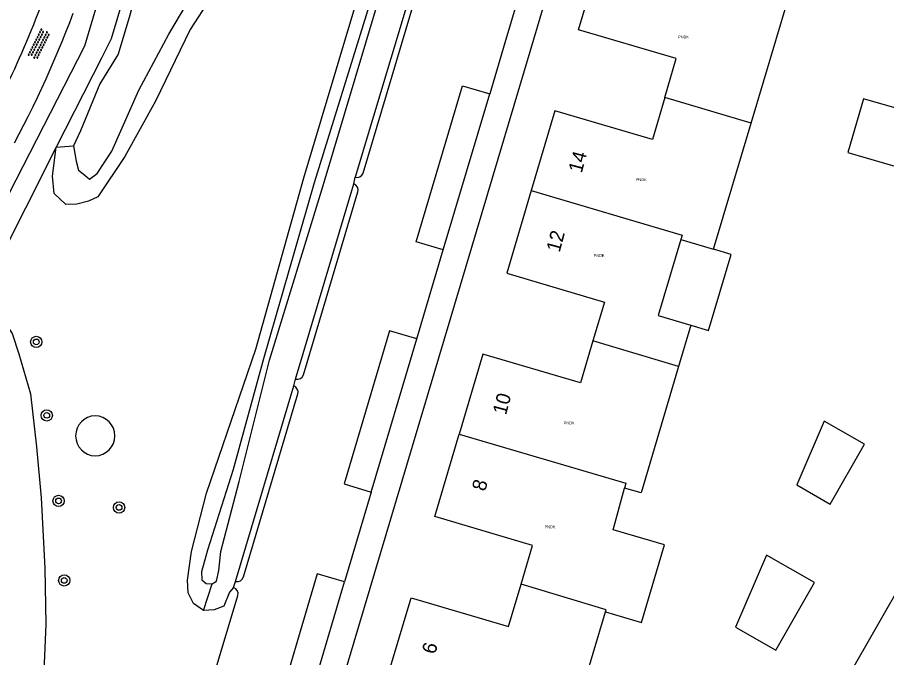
# Model space of a CAD drawing. Extents: x 131000 to 133013, y 393000 to 396501.
# Drawn here: x 131784.2 to 131845.9, y 393529.3 to 393574.7 of the extents above; entities that cross this region are included whole.
import ezdxf

# ---------------------------------------------------------------- set-up
doc = ezdxf.new("R2010")
doc.units = 0
for name, color, linetype in [('gg-anno-huisnummerreeks BGT', 7, 'Continuous'), ('gg-bbg-luifel en loopbrug', 7, 'Continuous'), ('gg-knt-onverhard', 7, 'Continuous'), ('gg-kwrk-kunstwerk niveau 01', 7, 'Continuous'), ('gt-symb-boom', 7, 'Continuous'), ('gt-symb-overige verharding', 7, 'Continuous'), ('gx-grn-maaiveld', 7, 'Continuous'), ('kenmerkpunt-x pandkandidaat', 7, 'Continuous')]:
    doc.layers.add(name, color=color, linetype=linetype)

# ---------------------------------------------------------------- blocks, each defined once
blk = doc.blocks.new('gt0-BOOM')
at = {"layer": 'gt-symb-boom'}
for radius in [0.4, 0.2]:
    blk.add_circle((0, 0), radius, dxfattribs=at)
blk = doc.blocks.new('gt0-OVH')
at = {"layer": 'gt-symb-overige verharding'}
for points in [[(-0.972, 0.298), (-0.967, 0.308), (-0.965, 0.319), (-0.966, 0.33), (-0.971, 0.34), (-0.978, 0.348), (-0.988, 0.353), (-0.999, 0.355), (-1.01, 0.354), (-1.02, 0.349), (-1.028, 0.342), (-1.033, 0.332), (-1.035, 0.321), (-1.034, 0.31), (-1.029, 0.3), (-1.022, 0.292), (-1.012, 0.287), (-1.001, 0.285), (-0.99, 0.286), (-0.98, 0.291)], [(-0.872, 0.106), (-0.867, 0.116), (-0.865, 0.126), (-0.866, 0.137), (-0.871, 0.147), (-0.878, 0.156), (-0.888, 0.161), (-0.899, 0.163), (-0.91, 0.162), (-0.92, 0.157), (-0.928, 0.15), (-0.933, 0.14), (-0.935, 0.129), (-0.934, 0.118), (-0.929, 0.108), (-0.922, 0.1), (-0.912, 0.095), (-0.901, 0.092), (-0.89, 0.094), (-0.88, 0.098)], [(-0.772, 0.298), (-0.767, 0.308), (-0.765, 0.319), (-0.766, 0.33), (-0.771, 0.34), (-0.778, 0.348), (-0.788, 0.353), (-0.799, 0.355), (-0.81, 0.354), (-0.82, 0.349), (-0.828, 0.342), (-0.833, 0.332), (-0.835, 0.321), (-0.834, 0.31), (-0.829, 0.3), (-0.822, 0.292), (-0.812, 0.287), (-0.801, 0.285), (-0.79, 0.286), (-0.78, 0.291)], [(-0.672, 0.106), (-0.667, 0.116), (-0.665, 0.126), (-0.666, 0.137), (-0.671, 0.147), (-0.678, 0.156), (-0.688, 0.161), (-0.699, 0.163), (-0.71, 0.162), (-0.72, 0.157), (-0.728, 0.15), (-0.733, 0.14), (-0.735, 0.129), (-0.734, 0.118), (-0.729, 0.108), (-0.722, 0.1), (-0.712, 0.095), (-0.701, 0.092), (-0.69, 0.094), (-0.68, 0.098)], [(-0.572, 0.298), (-0.567, 0.308), (-0.565, 0.319), (-0.566, 0.33), (-0.571, 0.34), (-0.578, 0.348), (-0.588, 0.353), (-0.599, 0.355), (-0.61, 0.354), (-0.62, 0.349), (-0.628, 0.342), (-0.633, 0.332), (-0.635, 0.321), (-0.634, 0.31), (-0.629, 0.3), (-0.622, 0.292), (-0.612, 0.287), (-0.601, 0.285), (-0.59, 0.286), (-0.58, 0.291)], [(-0.472, 0.106), (-0.467, 0.116), (-0.465, 0.126), (-0.466, 0.137), (-0.471, 0.147), (-0.478, 0.156), (-0.488, 0.161), (-0.499, 0.163), (-0.51, 0.162), (-0.52, 0.157), (-0.528, 0.15), (-0.533, 0.14), (-0.535, 0.129), (-0.534, 0.118), (-0.529, 0.108), (-0.522, 0.1), (-0.512, 0.095), (-0.501, 0.092), (-0.49, 0.094), (-0.48, 0.098)], [(-0.372, 0.298), (-0.367, 0.308), (-0.365, 0.319), (-0.366, 0.33), (-0.371, 0.34), (-0.378, 0.348), (-0.388, 0.353), (-0.399, 0.355), (-0.41, 0.354), (-0.42, 0.349), (-0.428, 0.342), (-0.433, 0.332), (-0.435, 0.321), (-0.434, 0.31), (-0.429, 0.3), (-0.422, 0.292), (-0.412, 0.287), (-0.401, 0.285), (-0.39, 0.286), (-0.38, 0.291)], [(-0.272, 0.106), (-0.267, 0.116), (-0.265, 0.126), (-0.266, 0.137), (-0.271, 0.147), (-0.278, 0.156), (-0.288, 0.161), (-0.299, 0.163), (-0.31, 0.162), (-0.32, 0.157), (-0.328, 0.15), (-0.333, 0.14), (-0.335, 0.129), (-0.334, 0.118), (-0.329, 0.108), (-0.322, 0.1), (-0.312, 0.095), (-0.301, 0.092), (-0.29, 0.094), (-0.28, 0.098)], [(-0.172, 0.298), (-0.167, 0.308), (-0.165, 0.319), (-0.166, 0.33), (-0.171, 0.34), (-0.178, 0.348), (-0.188, 0.353), (-0.199, 0.355), (-0.21, 0.354), (-0.22, 0.349), (-0.228, 0.342), (-0.233, 0.332), (-0.235, 0.321), (-0.234, 0.31), (-0.229, 0.3), (-0.222, 0.292), (-0.212, 0.287), (-0.201, 0.285), (-0.19, 0.286), (-0.18, 0.291)], [(-0.072, 0.106), (-0.067, 0.116), (-0.065, 0.126), (-0.066, 0.137), (-0.071, 0.147), (-0.078, 0.156), (-0.088, 0.161), (-0.099, 0.163), (-0.11, 0.162), (-0.12, 0.157), (-0.128, 0.15), (-0.133, 0.14), (-0.135, 0.129), (-0.134, 0.118), (-0.129, 0.108), (-0.122, 0.1), (-0.112, 0.095), (-0.101, 0.092), (-0.09, 0.094), (-0.08, 0.098)], [(0.028, 0.298), (0.033, 0.308), (0.035, 0.319), (0.034, 0.33), (0.029, 0.34), (0.022, 0.348), (0.012, 0.353), (0.001, 0.355), (-0.01, 0.354), (-0.02, 0.349), (-0.028, 0.342), (-0.033, 0.332), (-0.035, 0.321), (-0.034, 0.31), (-0.029, 0.3), (-0.022, 0.292), (-0.012, 0.287), (-0.001, 0.285), (0.01, 0.286), (0.02, 0.291)], [(0.128, 0.106), (0.133, 0.116), (0.135, 0.126), (0.134, 0.137), (0.129, 0.147), (0.122, 0.156), (0.112, 0.161), (0.101, 0.163), (0.09, 0.162), (0.08, 0.157), (0.072, 0.15), (0.067, 0.14), (0.065, 0.129), (0.066, 0.118), (0.071, 0.108), (0.078, 0.1), (0.088, 0.095), (0.099, 0.092), (0.11, 0.094), (0.12, 0.098)], [(0.228, 0.298), (0.233, 0.308), (0.235, 0.319), (0.234, 0.33), (0.229, 0.34), (0.222, 0.348), (0.212, 0.353), (0.201, 0.355), (0.19, 0.354), (0.18, 0.349), (0.172, 0.342), (0.167, 0.332), (0.165, 0.321), (0.166, 0.31), (0.171, 0.3), (0.178, 0.292), (0.188, 0.287), (0.199, 0.285), (0.21, 0.286), (0.22, 0.291)], [(0.328, 0.106), (0.333, 0.116), (0.335, 0.126), (0.334, 0.137), (0.329, 0.147), (0.322, 0.156), (0.312, 0.161), (0.301, 0.163), (0.29, 0.162), (0.28, 0.157), (0.272, 0.15), (0.267, 0.14), (0.265, 0.129), (0.266, 0.118), (0.271, 0.108), (0.278, 0.1), (0.288, 0.095), (0.299, 0.092), (0.31, 0.094), (0.32, 0.098)], [(0.428, 0.298), (0.433, 0.308), (0.435, 0.319), (0.434, 0.33), (0.429, 0.34), (0.422, 0.348), (0.412, 0.353), (0.401, 0.355), (0.39, 0.354), (0.38, 0.349), (0.372, 0.342), (0.367, 0.332), (0.365, 0.321), (0.366, 0.31), (0.371, 0.3), (0.378, 0.292), (0.388, 0.287), (0.399, 0.285), (0.41, 0.286), (0.42, 0.291)], [(0.528, 0.106), (0.533, 0.116), (0.535, 0.126), (0.534, 0.137), (0.529, 0.147), (0.522, 0.156), (0.512, 0.161), (0.501, 0.163), (0.49, 0.162), (0.48, 0.157), (0.472, 0.15), (0.467, 0.14), (0.465, 0.129), (0.466, 0.118), (0.471, 0.108), (0.478, 0.1), (0.488, 0.095), (0.499, 0.092), (0.51, 0.094), (0.52, 0.098)], [(0.628, 0.298), (0.633, 0.308), (0.635, 0.319), (0.634, 0.33), (0.629, 0.34), (0.622, 0.348), (0.612, 0.353), (0.601, 0.355), (0.59, 0.354), (0.58, 0.349), (0.572, 0.342), (0.567, 0.332), (0.565, 0.321), (0.566, 0.31), (0.571, 0.3), (0.578, 0.292), (0.588, 0.287), (0.599, 0.285), (0.61, 0.286), (0.62, 0.291)], [(0.728, 0.106), (0.733, 0.116), (0.735, 0.126), (0.734, 0.137), (0.729, 0.147), (0.722, 0.156), (0.712, 0.161), (0.701, 0.163), (0.69, 0.162), (0.68, 0.157), (0.672, 0.15), (0.667, 0.14), (0.665, 0.129), (0.666, 0.118), (0.671, 0.108), (0.678, 0.1), (0.688, 0.095), (0.699, 0.092), (0.71, 0.094), (0.72, 0.098)], [(0.828, 0.298), (0.833, 0.308), (0.835, 0.319), (0.834, 0.33), (0.829, 0.34), (0.822, 0.348), (0.812, 0.353), (0.801, 0.355), (0.79, 0.354), (0.78, 0.349), (0.772, 0.342), (0.767, 0.332), (0.765, 0.321), (0.766, 0.31), (0.771, 0.3), (0.778, 0.292), (0.788, 0.287), (0.799, 0.285), (0.81, 0.286), (0.82, 0.291)], [(0.928, 0.106), (0.933, 0.116), (0.935, 0.126), (0.934, 0.137), (0.929, 0.147), (0.922, 0.156), (0.912, 0.161), (0.901, 0.163), (0.89, 0.162), (0.88, 0.157), (0.872, 0.15), (0.867, 0.14), (0.865, 0.129), (0.866, 0.118), (0.871, 0.108), (0.878, 0.1), (0.888, 0.095), (0.899, 0.092), (0.91, 0.094), (0.92, 0.098)], [(1.028, 0.298), (1.033, 0.308), (1.035, 0.319), (1.034, 0.33), (1.029, 0.34), (1.022, 0.348), (1.012, 0.353), (1.001, 0.355), (0.99, 0.354), (0.98, 0.349), (0.972, 0.342), (0.967, 0.332), (0.965, 0.321), (0.966, 0.31), (0.971, 0.3), (0.978, 0.292), (0.988, 0.287), (0.999, 0.285), (1.01, 0.286), (1.02, 0.291)], [(-0.972, -0.142), (-0.967, -0.132), (-0.965, -0.121), (-0.966, -0.11), (-0.971, -0.1), (-0.978, -0.092), (-0.988, -0.087), (-0.999, -0.085), (-1.01, -0.086), (-1.02, -0.091), (-1.028, -0.098), (-1.033, -0.108), (-1.035, -0.119), (-1.034, -0.13), (-1.029, -0.14), (-1.022, -0.148), (-1.012, -0.153), (-1.001, -0.155), (-0.99, -0.154), (-0.98, -0.149)], [(-0.872, -0.334), (-0.867, -0.324), (-0.865, -0.314), (-0.866, -0.303), (-0.871, -0.293), (-0.878, -0.284), (-0.888, -0.279), (-0.899, -0.277), (-0.91, -0.278), (-0.92, -0.283), (-0.928, -0.29), (-0.933, -0.3), (-0.935, -0.311), (-0.934, -0.322), (-0.929, -0.332), (-0.922, -0.34), (-0.912, -0.345), (-0.901, -0.348), (-0.89, -0.346), (-0.88, -0.342)], [(-0.772, -0.142), (-0.767, -0.132), (-0.765, -0.121), (-0.766, -0.11), (-0.771, -0.1), (-0.778, -0.092), (-0.788, -0.087), (-0.799, -0.085), (-0.81, -0.086), (-0.82, -0.091), (-0.828, -0.098), (-0.833, -0.108), (-0.835, -0.119), (-0.834, -0.13), (-0.829, -0.14), (-0.822, -0.148), (-0.812, -0.153), (-0.801, -0.155), (-0.79, -0.154), (-0.78, -0.149)], [(-0.672, -0.334), (-0.667, -0.324), (-0.665, -0.314), (-0.666, -0.303), (-0.671, -0.293), (-0.678, -0.284), (-0.688, -0.279), (-0.699, -0.277), (-0.71, -0.278), (-0.72, -0.283), (-0.728, -0.29), (-0.733, -0.3), (-0.735, -0.311), (-0.734, -0.322), (-0.729, -0.332), (-0.722, -0.34), (-0.712, -0.345), (-0.701, -0.348), (-0.69, -0.346), (-0.68, -0.342)], [(-0.572, -0.142), (-0.567, -0.132), (-0.565, -0.121), (-0.566, -0.11), (-0.571, -0.1), (-0.578, -0.092), (-0.588, -0.087), (-0.599, -0.085), (-0.61, -0.086), (-0.62, -0.091), (-0.628, -0.098), (-0.633, -0.108), (-0.635, -0.119), (-0.634, -0.13), (-0.629, -0.14), (-0.622, -0.148), (-0.612, -0.153), (-0.601, -0.155), (-0.59, -0.154), (-0.58, -0.149)], [(-0.472, -0.334), (-0.467, -0.324), (-0.465, -0.314), (-0.466, -0.303), (-0.471, -0.293), (-0.478, -0.284), (-0.488, -0.279), (-0.499, -0.277), (-0.51, -0.278), (-0.52, -0.283), (-0.528, -0.29), (-0.533, -0.3), (-0.535, -0.311), (-0.534, -0.322), (-0.529, -0.332), (-0.522, -0.34), (-0.512, -0.345), (-0.501, -0.348), (-0.49, -0.346), (-0.48, -0.342)], [(-0.372, -0.142), (-0.367, -0.132), (-0.365, -0.121), (-0.366, -0.11), (-0.371, -0.1), (-0.378, -0.092), (-0.388, -0.087), (-0.399, -0.085), (-0.41, -0.086), (-0.42, -0.091), (-0.428, -0.098), (-0.433, -0.108), (-0.435, -0.119), (-0.434, -0.13), (-0.429, -0.14), (-0.422, -0.148), (-0.412, -0.153), (-0.401, -0.155), (-0.39, -0.154), (-0.38, -0.149)], [(-0.272, -0.334), (-0.267, -0.324), (-0.265, -0.314), (-0.266, -0.303), (-0.271, -0.293), (-0.278, -0.284), (-0.288, -0.279), (-0.299, -0.277), (-0.31, -0.278), (-0.32, -0.283), (-0.328, -0.29), (-0.333, -0.3), (-0.335, -0.311), (-0.334, -0.322), (-0.329, -0.332), (-0.322, -0.34), (-0.312, -0.345), (-0.301, -0.348), (-0.29, -0.346), (-0.28, -0.342)], [(-0.172, -0.142), (-0.167, -0.132), (-0.165, -0.121), (-0.166, -0.11), (-0.171, -0.1), (-0.178, -0.092), (-0.188, -0.087), (-0.199, -0.085), (-0.21, -0.086), (-0.22, -0.091), (-0.228, -0.098), (-0.233, -0.108), (-0.235, -0.119), (-0.234, -0.13), (-0.229, -0.14), (-0.222, -0.148), (-0.212, -0.153), (-0.201, -0.155), (-0.19, -0.154), (-0.18, -0.149)], [(-0.072, -0.334), (-0.067, -0.324), (-0.065, -0.314), (-0.066, -0.303), (-0.071, -0.293), (-0.078, -0.284), (-0.088, -0.279), (-0.099, -0.277), (-0.11, -0.278), (-0.12, -0.283), (-0.128, -0.29), (-0.133, -0.3), (-0.135, -0.311), (-0.134, -0.322), (-0.129, -0.332), (-0.122, -0.34), (-0.112, -0.345), (-0.101, -0.348), (-0.09, -0.346), (-0.08, -0.342)], [(0.028, -0.142), (0.033, -0.132), (0.035, -0.121), (0.034, -0.11), (0.029, -0.1), (0.022, -0.092), (0.012, -0.087), (0.001, -0.085), (-0.01, -0.086), (-0.02, -0.091), (-0.028, -0.098), (-0.033, -0.108), (-0.035, -0.119), (-0.034, -0.13), (-0.029, -0.14), (-0.022, -0.148), (-0.012, -0.153), (-0.001, -0.155), (0.01, -0.154), (0.02, -0.149)], [(0.128, -0.334), (0.133, -0.324), (0.135, -0.314), (0.134, -0.303), (0.129, -0.293), (0.122, -0.284), (0.112, -0.279), (0.101, -0.277), (0.09, -0.278), (0.08, -0.283), (0.072, -0.29), (0.067, -0.3), (0.065, -0.311), (0.066, -0.322), (0.071, -0.332), (0.078, -0.34), (0.088, -0.345), (0.099, -0.348), (0.11, -0.346), (0.12, -0.342)], [(0.228, -0.142), (0.233, -0.132), (0.235, -0.121), (0.234, -0.11), (0.229, -0.1), (0.222, -0.092), (0.212, -0.087), (0.201, -0.085), (0.19, -0.086), (0.18, -0.091), (0.172, -0.098), (0.167, -0.108), (0.165, -0.119), (0.166, -0.13), (0.171, -0.14), (0.178, -0.148), (0.188, -0.153), (0.199, -0.155), (0.21, -0.154), (0.22, -0.149)], [(0.328, -0.334), (0.333, -0.324), (0.335, -0.314), (0.334, -0.303), (0.329, -0.293), (0.322, -0.284), (0.312, -0.279), (0.301, -0.277), (0.29, -0.278), (0.28, -0.283), (0.272, -0.29), (0.267, -0.3), (0.265, -0.311), (0.266, -0.322), (0.271, -0.332), (0.278, -0.34), (0.288, -0.345), (0.299, -0.348), (0.31, -0.346), (0.32, -0.342)], [(0.428, -0.142), (0.433, -0.132), (0.435, -0.121), (0.434, -0.11), (0.429, -0.1), (0.422, -0.092), (0.412, -0.087), (0.401, -0.085), (0.39, -0.086), (0.38, -0.091), (0.372, -0.098), (0.367, -0.108), (0.365, -0.119), (0.366, -0.13), (0.371, -0.14), (0.378, -0.148), (0.388, -0.153), (0.399, -0.155), (0.41, -0.154), (0.42, -0.149)], [(0.528, -0.334), (0.533, -0.324), (0.535, -0.314), (0.534, -0.303), (0.529, -0.293), (0.522, -0.284), (0.512, -0.279), (0.501, -0.277), (0.49, -0.278), (0.48, -0.283), (0.472, -0.29), (0.467, -0.3), (0.465, -0.311), (0.466, -0.322), (0.471, -0.332), (0.478, -0.34), (0.488, -0.345), (0.499, -0.348), (0.51, -0.346), (0.52, -0.342)], [(0.628, -0.142), (0.633, -0.132), (0.635, -0.121), (0.634, -0.11), (0.629, -0.1), (0.622, -0.092), (0.612, -0.087), (0.601, -0.085), (0.59, -0.086), (0.58, -0.091), (0.572, -0.098), (0.567, -0.108), (0.565, -0.119), (0.566, -0.13), (0.571, -0.14), (0.578, -0.148), (0.588, -0.153), (0.599, -0.155), (0.61, -0.154), (0.62, -0.149)], [(0.728, -0.334), (0.733, -0.324), (0.735, -0.314), (0.734, -0.303), (0.729, -0.293), (0.722, -0.284), (0.712, -0.279), (0.701, -0.277), (0.69, -0.278), (0.68, -0.283), (0.672, -0.29), (0.667, -0.3), (0.665, -0.311), (0.666, -0.322), (0.671, -0.332), (0.678, -0.34), (0.688, -0.345), (0.699, -0.348), (0.71, -0.346), (0.72, -0.342)], [(0.828, -0.142), (0.833, -0.132), (0.835, -0.121), (0.834, -0.11), (0.829, -0.1), (0.822, -0.092), (0.812, -0.087), (0.801, -0.085), (0.79, -0.086), (0.78, -0.091), (0.772, -0.098), (0.767, -0.108), (0.765, -0.119), (0.766, -0.13), (0.771, -0.14), (0.778, -0.148), (0.788, -0.153), (0.799, -0.155), (0.81, -0.154), (0.82, -0.149)], [(0.928, -0.334), (0.933, -0.324), (0.935, -0.314), (0.934, -0.303), (0.929, -0.293), (0.922, -0.284), (0.912, -0.279), (0.901, -0.277), (0.89, -0.278), (0.88, -0.283), (0.872, -0.29), (0.867, -0.3), (0.865, -0.311), (0.866, -0.322), (0.871, -0.332), (0.878, -0.34), (0.888, -0.345), (0.899, -0.348), (0.91, -0.346), (0.92, -0.342)], [(1.028, -0.142), (1.033, -0.132), (1.035, -0.121), (1.034, -0.11), (1.029, -0.1), (1.022, -0.092), (1.012, -0.087), (1.001, -0.085), (0.99, -0.086), (0.98, -0.091), (0.972, -0.098), (0.967, -0.108), (0.965, -0.119), (0.966, -0.13), (0.971, -0.14), (0.978, -0.148), (0.988, -0.153), (0.999, -0.155), (1.01, -0.154), (1.02, -0.149)]]:
    blk.add_lwpolyline(points, close=True, dxfattribs=at)

msp = doc.modelspace()

# ---------------------------------------------------------------- linework, layer by layer
at = {"layer": 'gg-bbg-luifel en loopbrug'}
msp.add_line((131831.27, 393558.985), (131833.569, 393558.299), dxfattribs=at)
for points in [[(131831.27, 393558.985), (131829.663, 393553.598), (131831.971, 393552.912)], [(131831.971, 393552.912), (131833.225, 393552.539), (131834.831, 393557.923), (131833.569, 393558.299)]]:
    msp.add_lwpolyline(points, dxfattribs=at)
at = {"layer": 'gg-knt-onverhard'}
msp.add_arc((131711.634, 393604.015), 79.523, 330.61623, 340.48685, dxfattribs=at)
at = {"layer": 'gg-kwrk-kunstwerk niveau 01'}
for points in [[(131849.405, 393567.468), (131844.216, 393568.977), (131843.107, 393565.168), (131848.296, 393563.658), (131849.405, 393567.468)], [(131841.858, 393540.229), (131844.29, 393544.484), (131841.43, 393546.12), (131839.48, 393541.589), (131841.858, 393540.229)], [(131835.139, 393531.5), (131838.004, 393529.866), (131840.74, 393534.663), (131837.336, 393536.605), (131835.139, 393531.5)]]:
    msp.add_lwpolyline(points, dxfattribs=at)
at = {"layer": 'gx-grn-maaiveld'}
for p, q in [((131812.321, 393577.255), (131808.161, 393563.412)), ((131808.737, 393563.703), (131812.612, 393576.684)), ((131814.419, 393558.262), (131817.709, 393569.316)), ((131836.239, 393567.253), (131830.125, 393569.058)), ((131833.569, 393558.299), (131836.239, 393567.253)), ((131786.977, 393565.55), (131788.205, 393565.642)), ((131808.071, 393562.94), (131808.161, 393563.412)), ((131803.942, 393549.093), (131808.071, 393562.94)), ((131804.511, 393549.39), (131808.357, 393562.366)), ((131812.539, 393551.943), (131814.419, 393558.262)), ((131831.971, 393552.912), (131831.103, 393549.99)), ((131809.309, 393541.085), (131812.539, 393551.943)), ((131831.103, 393549.99), (131825.029, 393551.796)), ((131799.694, 393534.73), (131803.819, 393548.614)), ((131803.819, 393548.614), (131803.942, 393549.093)), ((131800.254, 393535.071), (131804.114, 393548.049)), ((131809.309, 393541.085), (131807.414, 393534.717)), ((131842.716, 393527.276), (131847.183, 393535.09)), ((131797.419, 393532.683), (131798.018, 393534.58)), ((131799.547, 393534.32), (131799.694, 393534.73)), ((131804.192, 393523.89), (131807.414, 393534.717)), ((131796.114, 393521.295), (131799.856, 393533.751))]:
    msp.add_line(p, q, dxfattribs=at)
for points in [[(131798.018, 393534.58), (131798.348, 393534.766), (131798.501, 393535.531), (131798.633, 393536.858), (131799.941, 393541.824), (131802.105, 393550.443), (131805.889, 393562.825), (131809.673, 393575.457), (131813.175, 393587.644), (131816.997, 393599.497), (131817.742, 393602.597), (131819.099, 393606.501), (131820.513, 393610.351), (131822.762, 393613.333), (131825.407, 393615.94), (131828.176, 393618.18), (131831.806, 393620.98), (131843.784, 393630.908), (131854.149, 393639.623), (131859.745, 393643.867), (131863.364, 393646.398), (131864.487, 393646.819), (131865.087, 393647.085), (131865.418, 393647.443)], [(131780.191, 393555.344), (131781.2, 393557.543), (131789.001, 393572.723), (131791.282, 393580.452), (131791.376, 393580.771), (131793.151, 393586.786), (131794.973, 393603.862), (131795.471, 393613.469)], [(131830.381, 393605.406), (131820.552, 393572.299), (131802.733, 393512.525)], [(131793.814, 393583.151), (131790.87, 393573.226), (131790.197, 393571.898), (131786.977, 393565.55)], [(131794.643, 393581.68), (131793.968, 393580.68), (131793.078, 393578.27), (131792.187, 393574.89), (131791.375, 393572.139), (131790.065, 393570.043), (131788.702, 393566.69), (131788.205, 393565.642)], [(131788.205, 393565.642), (131788.396, 393564.547), (131788.56, 393563.899), (131788.991, 393563.554), (131789.328, 393563.272), (131789.875, 393563.675), (131790.926, 393565.255), (131792.832, 393569.587), (131794.946, 393573.561), (131798.401, 393579.385)], [(131830.125, 393569.058), (131830.941, 393571.822), (131824.016, 393573.866), (131825.745, 393579.722)], [(131799.362, 393578.349), (131796.48, 393573.882), (131794.02, 393568.791), (131791.831, 393564.884), (131789.918, 393562.027), (131789.261, 393561.71), (131788.427, 393561.493), (131787.664, 393561.47), (131786.821, 393562.266), (131786.705, 393563.494), (131786.977, 393565.55)], [(131836.239, 393567.253), (131838.861, 393576.048), (131837.637, 393576.358)], [(131797.419, 393532.683), (131796.708, 393533.184), (131796.325, 393533.949), (131796.292, 393534.843), (131796.57, 393536.865), (131797.636, 393541.001), (131801.134, 393551.21), (131804.524, 393563.363), (131808.281, 393575.923)], [(131819.586, 393575.629), (131818.783, 393572.927), (131817.709, 393569.316)], [(131788.159, 393575.022), (131787.902, 393574.348), (131787.64, 393573.676), (131787.37, 393573.006), (131787.095, 393572.339), (131786.813, 393571.675), (131786.524, 393571.013), (131786.23, 393570.355), (131785.929, 393569.699), (131785.621, 393569.046), (131785.308, 393568.396), (131784.988, 393567.749), (131784.662, 393567.105), (131784.33, 393566.465), (131783.992, 393565.827)], [(131809.155, 393575.587), (131805.258, 393563.013), (131801.663, 393550.537), (131799.525, 393542.69), (131797.709, 393536.969), (131797.272, 393535.428), (131797.305, 393534.864), (131797.602, 393534.604), (131798.018, 393534.58)], [(131814.419, 393558.262), (131812.488, 393558.836), (131815.774, 393569.891), (131817.709, 393569.316)], [(131830.125, 393569.058), (131829.245, 393566.077), (131822.32, 393568.121), (131820.65, 393562.462)], [(131786.977, 393565.55), (131782.588, 393556.897), (131781.499, 393554.538)], [(131820.65, 393562.462), (131818.92, 393556.602), (131825.844, 393554.558), (131825.029, 393551.796)], [(131820.65, 393562.462), (131831.364, 393559.3), (131831.27, 393558.985)], [(131781.499, 393554.538), (131782.085, 393554.177), (131783.2, 393553.266), (131783.85, 393552.328), (131784.329, 393550.874), (131785.158, 393548.051), (131785.581, 393544.298), (131785.912, 393540.669), (131786.172, 393535.68), (131786.236, 393531.694), (131786.041, 393527.286)], [(131812.539, 393551.943), (131810.614, 393552.516), (131807.382, 393541.659), (131809.309, 393541.085)], [(131825.029, 393551.796), (131824.151, 393548.823), (131817.227, 393550.867), (131815.553, 393545.195)], [(131831.103, 393549.99), (131828.438, 393541.024), (131827.275, 393541.361)], [(131819.936, 393534.543), (131820.748, 393537.295), (131813.824, 393539.339), (131815.553, 393545.195)], [(131815.553, 393545.195), (131827.371, 393541.706), (131827.275, 393541.361)], [(131825.927, 393532.596), (131828.476, 393531.839), (131830.111, 393537.351), (131826.459, 393538.412), (131827.275, 393541.361)], [(131807.414, 393534.717), (131805.481, 393535.286), (131802.291, 393524.45), (131804.192, 393523.89)], [(131810.471, 393527.981), (131812.128, 393533.594), (131819.053, 393531.55), (131819.936, 393534.543)], [(131825.927, 393532.596), (131825.968, 393532.731), (131819.936, 393534.543)], [(131799.547, 393534.32), (131799.267, 393533.986), (131798.85, 393532.996), (131798.162, 393532.731), (131797.419, 393532.683)], [(131820.984, 393524.475), (131823.286, 393523.796), (131825.927, 393532.596)]]:
    msp.add_lwpolyline(points, dxfattribs=at)
for centre, radius, start, end in [((131808.3, 393563.852), 0.462, 252.4634, 341.14317), ((131807.913, 393562.503), 0.465, 342.85463, 70.11565), ((131804.07, 393549.541), 0.466, 254.02793, 341.09833), ((131803.616, 393548.149), 0.508, 348.68306, 66.45722), ((131789.77, 393545.071), 1.421, 91.20232, 268.79768), ((131789.71, 393545.071), 1.421, 271.20232, 88.79768), ((131799.77, 393535.236), 0.511, 261.45613, 341.22073), ((131799.374, 393533.858), 0.494, 347.50837, 69.50068)]:
    msp.add_arc(centre, radius, start, end, dxfattribs=at)

# ---------------------------------------------------------------- block references
at = {"layer": 'gt-symb-boom'}
for p in [(131785.556, 393551.731), (131786.301, 393546.52), (131787.139, 393540.457), (131791.43, 393539.99), (131787.54, 393534.819)]:
    msp.add_blockref('gt0-BOOM', p, dxfattribs=at)
at = {"layer": 'gt-symb-overige verharding', "rotation": 63.332497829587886}
msp.add_blockref('gt0-OVH', (131785.753, 393572.84), dxfattribs=at)

# ---------------------------------------------------------------- texts
at = {"layer": 'gg-anno-huisnummerreeks BGT'}
for s, p in [('14', (131824.233, 393563.659)), ('12', (131822.665, 393558.033)), ('10', (131818.862, 393546.5)), ('8', (131817.389, 393541.094)), ('6', (131813.844, 393529.538))]:
    msp.add_text(s, height=1, rotation=75, dxfattribs=at).set_placement(p)
at = {"layer": 'kenmerkpunt-x pandkandidaat'}
for p in [(131831.068, 393573.256), (131828.074, 393563.137), (131825.075, 393557.761), (131822.957, 393545.883), (131821.597, 393538.517)]:
    msp.add_text('PNDK', height=0.2, dxfattribs=at).set_placement(p)

doc.saveas('drawing.dxf')
